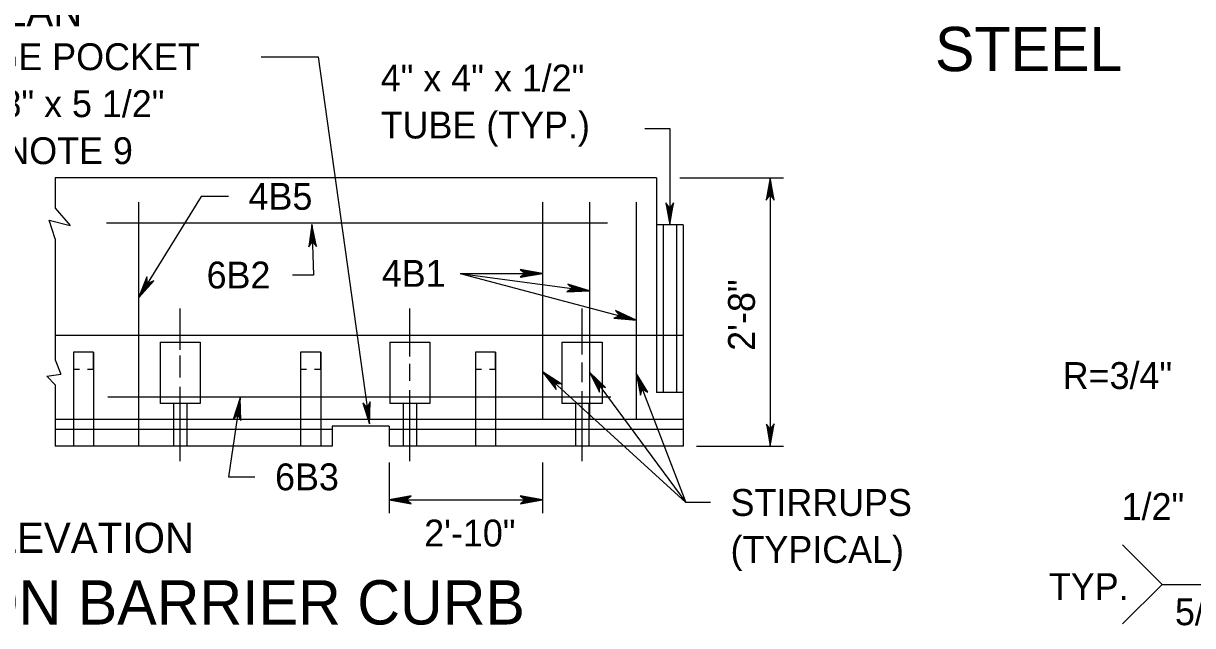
# Model space of a CAD drawing. Extents: x 499883 to 500983, y 499104 to 499764.
# Drawn here: x 500394.2 to 500568.6, y 499221.5 to 499311.2 of the extents above; entities that cross this region are included whole.
import ezdxf

# ---------------------------------------------------------------- set-up
doc = ezdxf.new("R2010")
doc.units = 0
for name, color, linetype in [('1', 7, 'Continuous'), ('24', 7, 'Continuous'), ('3', 7, 'Continuous'), ('5', 7, 'Continuous')]:
    doc.layers.add(name, color=color, linetype=linetype)

msp = doc.modelspace()

# ---------------------------------------------------------------- linework, layer by layer
at = {"layer": '1'}
for p, q in [((500417.6, 499262.54), (500417.6, 499268.7)), ((500451.89, 499261.59), (500451.89, 499268.7)), ((500477.56, 499261.86), (500477.56, 499268.7)), ((500417.6, 499258.44), (500417.6, 499261.72)), ((500451.89, 499257.94), (500451.89, 499260.49)), ((500477.56, 499257.75), (500477.56, 499260.67)), ((500417.6, 499245.98), (500417.6, 499257.07)), ((500451.89, 499245.98), (500451.89, 499256.57)), ((500477.56, 499245.98), (500477.56, 499256.39))]:
    msp.add_line(p, q, dxfattribs=at)
at = {"layer": '24'}
for points in [[(500490.64, 499281.18), (500491.22, 499284.46), (500490.64, 499283.67), (500490.07, 499284.44), (500490.64, 499281.18), (500490.64, 499281.4), (500491.18, 499284.36), (500490.64, 499283.61), (500490.12, 499284.31), (500490.63, 499281.52), (500490.64, 499281.63), (500491.09, 499284.17), (500490.64, 499283.6), (500490.19, 499284.18), (500490.64, 499281.68), (500490.63, 499281.79), (500491.03, 499284.01), (500490.64, 499283.57), (500490.24, 499284.01), (500490.63, 499282.1), (500490.63, 499282.29), (500490.94, 499283.84), (500490.65, 499283.54), (500490.33, 499283.86), (500490.64, 499282.32), (500490.65, 499282.49), (500490.85, 499283.66), (500490.63, 499283.44), (500490.4, 499283.68), (500490.64, 499282.65), (500490.66, 499282.82), (500490.79, 499283.52), (500490.64, 499283.41), (500490.46, 499283.6), (500490.64, 499282.91), (500490.75, 499283.36), (500490.63, 499283.3), (500490.5, 499283.5), (500490.63, 499283.02), (500490.7, 499283.32), (500490.6, 499283.19), (500490.54, 499283.34), (500490.64, 499283.2), (500490.65, 499283.27)], [(500437.28, 499281.23), (500437.49, 499273.71), (500434.37, 499273.71)], [(500437.28, 499281.23), (500436.79, 499277.89), (500437.35, 499278.7), (500437.95, 499277.94), (500437.28, 499281.23), (500437.29, 499281.01), (500436.83, 499277.98), (500437.36, 499278.76), (500437.9, 499278.07), (500437.3, 499280.89), (500437.29, 499280.78), (500436.91, 499278.19), (500437.36, 499278.78), (500437.82, 499278.2), (500437.29, 499280.73), (500437.31, 499280.62), (500436.97, 499278.35), (500437.35, 499278.8), (500437.77, 499278.37), (500437.32, 499280.3), (500437.33, 499280.11), (500437.05, 499278.52), (500437.34, 499278.84), (500437.68, 499278.52), (500437.31, 499280.07), (500437.31, 499279.9), (500437.14, 499278.7), (500437.36, 499278.94), (500437.6, 499278.7), (500437.32, 499279.73), (500437.31, 499279.57), (500437.19, 499278.85), (500437.35, 499278.97), (500437.53, 499278.78), (500437.33, 499279.48), (500437.23, 499279.01), (500437.36, 499279.08), (500437.49, 499278.88), (500437.35, 499279.36), (500437.28, 499279.06), (500437.38, 499279.19), (500437.44, 499279.04), (500437.34, 499279.19), (500437.33, 499279.11)], [(500411.42, 499270.29), (500413.68, 499272.83), (500412.76, 499272.46), (500412.67, 499273.43), (500411.42, 499270.29), (500411.53, 499270.48), (500413.6, 499272.78), (500412.72, 499272.41), (500412.64, 499273.29), (500411.59, 499270.59), (500411.66, 499270.68), (500413.42, 499272.65), (500412.71, 499272.4), (500412.64, 499273.14), (500411.69, 499270.72), (500411.73, 499270.82), (500413.27, 499272.54), (500412.7, 499272.37), (500412.59, 499272.97), (500411.9, 499271.1), (500412, 499271.26), (500413.11, 499272.44), (500412.69, 499272.34), (500412.58, 499272.8), (500412.03, 499271.28), (500412.14, 499271.43), (500412.94, 499272.34), (500412.62, 499272.26), (500412.55, 499272.6), (500412.21, 499271.57), (500412.31, 499271.71), (500412.81, 499272.25), (500412.61, 499272.23), (500412.56, 499272.49), (500412.35, 499271.79), (500412.69, 499272.13), (500412.54, 499272.14), (500412.54, 499272.38), (500412.39, 499271.9), (500412.62, 499272.12), (500412.47, 499272.06), (500412.49, 499272.22), (500412.5, 499272.05), (500412.55, 499272.1)], [(500471.66, 499273.95), (500468.31, 499274.54), (500469.11, 499273.95), (500468.33, 499273.37), (500471.66, 499273.95), (500471.44, 499273.95), (500468.41, 499274.5), (500469.18, 499273.94), (500468.47, 499273.41), (500471.32, 499273.94), (500471.21, 499273.95), (500468.61, 499274.41), (500469.19, 499273.94), (500468.59, 499273.49), (500471.16, 499273.95), (500471.05, 499273.94), (500468.78, 499274.35), (500469.22, 499273.95), (500468.77, 499273.54), (500470.72, 499273.93), (500470.53, 499273.94), (500468.94, 499274.26), (500469.25, 499273.96), (500468.92, 499273.63), (500470.5, 499273.95), (500470.32, 499273.96), (500469.13, 499274.17), (500469.36, 499273.93), (500469.11, 499273.71), (500470.16, 499273.95), (500469.99, 499273.97), (500469.27, 499274.11), (500469.39, 499273.94), (500469.19, 499273.77), (500469.9, 499273.95), (500469.43, 499274.06), (500469.5, 499273.94), (500469.29, 499273.81), (500469.78, 499273.93), (500469.48, 499274.01), (500469.6, 499273.91), (500469.46, 499273.85), (500469.6, 499273.94), (500469.53, 499273.96)], [(500478.66, 499271.34), (500475.42, 499272.37), (500476.13, 499271.68), (500475.28, 499271.21), (500478.66, 499271.34), (500478.44, 499271.36), (500475.51, 499272.32), (500476.19, 499271.66), (500475.42, 499271.23), (500478.32, 499271.37), (500478.21, 499271.4), (500475.7, 499272.21), (500476.21, 499271.66), (500475.55, 499271.29), (500478.16, 499271.41), (500478.04, 499271.4), (500475.85, 499272.12), (500476.23, 499271.67), (500475.73, 499271.32), (500477.72, 499271.45), (500477.54, 499271.47), (500476, 499272.01), (500476.27, 499271.67), (500475.9, 499271.39), (500477.51, 499271.49), (500477.33, 499271.53), (500476.17, 499271.89), (500476.37, 499271.63), (500476.09, 499271.44), (500477.17, 499271.54), (500477, 499271.58), (500476.31, 499271.81), (500476.4, 499271.64), (500476.19, 499271.48), (500476.91, 499271.57), (500476.46, 499271.75), (500476.51, 499271.61), (500476.29, 499271.51), (500476.79, 499271.57), (500476.5, 499271.69), (500476.61, 499271.57), (500476.46, 499271.53), (500476.62, 499271.61), (500476.54, 499271.63)], [(500485.65, 499266.99), (500482.57, 499268.42), (500483.19, 499267.64), (500482.28, 499267.28), (500485.65, 499266.99), (500485.44, 499267.04), (500482.65, 499268.36), (500483.25, 499267.62), (500482.42, 499267.29), (500485.32, 499267.06), (500485.21, 499267.11), (500482.82, 499268.22), (500483.26, 499267.62), (500482.57, 499267.33), (500485.16, 499267.12), (500485.05, 499267.13), (500482.96, 499268.11), (500483.29, 499267.62), (500482.75, 499267.34), (500484.74, 499267.22), (500484.56, 499267.26), (500483.1, 499267.99), (500483.33, 499267.62), (500482.92, 499267.38), (500484.53, 499267.29), (500484.36, 499267.35), (500483.25, 499267.85), (500483.42, 499267.57), (500483.12, 499267.41), (500484.2, 499267.38), (500484.04, 499267.44), (500483.38, 499267.75), (500483.45, 499267.57), (500483.22, 499267.44), (500483.95, 499267.44), (500483.52, 499267.67), (500483.56, 499267.53), (500483.33, 499267.46), (500483.83, 499267.46), (500483.55, 499267.61), (500483.65, 499267.48), (500483.49, 499267.46), (500483.66, 499267.51), (500483.59, 499267.55)], [(500471.66, 499259.27), (500473.69, 499256.64), (500473.51, 499257.59), (500474.46, 499257.5), (500471.66, 499259.27), (500471.83, 499259.13), (500473.66, 499256.73), (500473.47, 499257.64), (500474.33, 499257.55), (500471.92, 499259.06), (500471.99, 499258.97), (500473.57, 499256.93), (500473.45, 499257.65), (500474.18, 499257.58), (500472.03, 499258.94), (500472.12, 499258.88), (500473.49, 499257.09), (500473.43, 499257.66), (500474.03, 499257.66), (500472.35, 499258.66), (500472.49, 499258.54), (500473.43, 499257.26), (500473.4, 499257.68), (500473.86, 499257.7), (500472.5, 499258.5), (500472.63, 499258.38), (500473.36, 499257.45), (500473.34, 499257.76), (500473.67, 499257.77), (500472.75, 499258.28), (500472.86, 499258.16), (500473.29, 499257.58), (500473.31, 499257.78), (500473.57, 499257.78), (500472.94, 499258.11), (500473.2, 499257.72), (500473.24, 499257.86), (500473.47, 499257.82), (500473.03, 499258.05), (500473.2, 499257.79), (500473.18, 499257.95), (500473.32, 499257.89), (500473.16, 499257.92), (500473.2, 499257.86)], [(500478.66, 499259.23), (500480.14, 499256.25), (500480.14, 499257.23), (500481.05, 499256.95), (500478.66, 499259.23), (500478.79, 499259.06), (500480.12, 499256.35), (500480.11, 499257.28), (500480.94, 499257.03), (500478.87, 499258.97), (500478.92, 499258.87), (500480.07, 499256.56), (500480.1, 499257.29), (500480.81, 499257.09), (500478.95, 499258.83), (500479.03, 499258.76), (500480.03, 499256.73), (500480.08, 499257.31), (500480.66, 499257.19), (500479.22, 499258.5), (500479.33, 499258.35), (500480, 499256.92), (500480.05, 499257.33), (500480.51, 499257.26), (500479.33, 499258.32), (500479.43, 499258.17), (500479.96, 499257.11), (500480.01, 499257.43), (500480.34, 499257.37), (500479.53, 499258.05), (500479.62, 499257.91), (500479.93, 499257.26), (500479.99, 499257.45), (500480.24, 499257.4), (500479.68, 499257.85), (500479.87, 499257.41), (500479.93, 499257.54), (500480.15, 499257.45), (500479.76, 499257.76), (500479.88, 499257.48), (500479.89, 499257.64), (500480.02, 499257.56), (500479.86, 499257.62), (500479.89, 499257.55)], [(500485.65, 499259.08), (500486.28, 499255.82), (500486.54, 499256.75), (500487.35, 499256.24), (500485.65, 499259.08), (500485.74, 499258.88), (500486.29, 499255.92), (500486.53, 499256.81), (500487.26, 499256.35), (500485.79, 499258.77), (500485.81, 499258.67), (500486.3, 499256.13), (500486.52, 499256.83), (500487.15, 499256.44), (500485.83, 499258.62), (500485.88, 499258.52), (500486.3, 499256.31), (500486.51, 499256.85), (500487.04, 499256.58), (500486, 499258.23), (500486.06, 499258.06), (500486.32, 499256.49), (500486.49, 499256.88), (500486.91, 499256.69), (500486.06, 499258.02), (500486.11, 499257.85), (500486.34, 499256.69), (500486.47, 499256.98), (500486.77, 499256.83), (500486.18, 499257.71), (500486.22, 499257.55), (500486.35, 499256.84), (500486.45, 499257.01), (500486.69, 499256.89), (500486.27, 499257.47), (500486.33, 499257.01), (500486.42, 499257.11), (500486.61, 499256.97), (500486.32, 499257.37), (500486.36, 499257.06), (500486.41, 499257.22), (500486.52, 499257.1), (500486.38, 499257.2), (500486.39, 499257.13)], [(500426.57, 499255.39), (500424.82, 499243.64), (500428.77, 499243.64)], [(500426.57, 499255.39), (500425.5, 499252.19), (500426.2, 499252.89), (500426.66, 499252.04), (500426.57, 499255.39), (500426.55, 499255.17), (500425.56, 499252.28), (500426.22, 499252.95), (500426.63, 499252.18), (500426.54, 499255.05), (500426.51, 499254.95), (500425.67, 499252.46), (500426.22, 499252.97), (500426.58, 499252.31), (500426.5, 499254.9), (500426.5, 499254.79), (500425.77, 499252.62), (500426.22, 499252.99), (500426.55, 499252.49), (500426.45, 499254.47), (500426.43, 499254.28), (500425.87, 499252.77), (500426.21, 499253.03), (500426.49, 499252.65), (500426.4, 499254.25), (500426.37, 499254.08), (500425.99, 499252.93), (500426.25, 499253.13), (500426.44, 499252.85), (500426.35, 499253.91), (500426.31, 499253.75), (500426.07, 499253.07), (500426.25, 499253.16), (500426.4, 499252.94), (500426.32, 499253.66), (500426.14, 499253.22), (500426.27, 499253.27), (500426.37, 499253.05), (500426.32, 499253.55), (500426.19, 499253.25), (500426.31, 499253.37), (500426.35, 499253.21), (500426.28, 499253.37), (500426.25, 499253.3)], [(500445.86, 499251.52), (500445.98, 499254.84), (500445.51, 499253.98), (500444.84, 499254.66), (500445.86, 499251.52), (500445.82, 499251.73), (500445.95, 499254.74), (500445.52, 499253.92), (500444.91, 499254.54), (500445.8, 499251.84), (500445.8, 499251.96), (500445.89, 499254.53), (500445.52, 499253.91), (500445, 499254.42), (500445.79, 499252), (500445.76, 499252.11), (500445.85, 499254.36), (500445.53, 499253.88), (500445.07, 499254.26), (500445.72, 499252.42), (500445.69, 499252.61), (500445.79, 499254.19), (500445.54, 499253.85), (500445.18, 499254.13), (500445.7, 499252.64), (500445.69, 499252.82), (500445.72, 499254), (500445.53, 499253.75), (500445.28, 499253.96), (500445.66, 499252.97), (500445.65, 499253.14), (500445.68, 499253.85), (500445.54, 499253.72), (500445.35, 499253.88), (500445.62, 499253.22), (500445.67, 499253.69), (500445.55, 499253.61), (500445.4, 499253.79), (500445.59, 499253.33), (500445.62, 499253.64), (500445.54, 499253.5), (500445.46, 499253.64), (500445.57, 499253.51), (500445.58, 499253.58)], [(500448.77, 499240.21), (500452.09, 499239.63), (500451.3, 499240.21), (500452.07, 499240.79), (500448.77, 499240.21), (500448.99, 499240.22), (500452, 499239.67), (500451.24, 499240.22), (500451.94, 499240.75), (500449.11, 499240.23), (500449.22, 499240.21), (500451.8, 499239.76), (500451.22, 499240.22), (500451.81, 499240.67), (500449.27, 499240.21), (500449.38, 499240.23), (500451.63, 499239.82), (500451.19, 499240.21), (500451.64, 499240.62), (500449.7, 499240.23), (500449.89, 499240.23), (500451.47, 499239.91), (500451.16, 499240.2), (500451.49, 499240.53), (500449.92, 499240.21), (500450.1, 499240.2), (500451.29, 499240), (500451.06, 499240.23), (500451.3, 499240.46), (500450.26, 499240.21), (500450.43, 499240.2), (500451.14, 499240.06), (500451.02, 499240.22), (500451.22, 499240.4), (500450.52, 499240.21), (500450.98, 499240.1), (500450.91, 499240.23), (500451.12, 499240.36), (500450.63, 499240.23), (500450.94, 499240.15), (500450.81, 499240.25), (500450.96, 499240.31), (500450.81, 499240.22), (500450.89, 499240.2)], [(500471.66, 499240.21), (500468.34, 499240.8), (500469.13, 499240.21), (500468.36, 499239.64), (500471.66, 499240.21), (500471.44, 499240.21), (500468.43, 499240.76), (500469.2, 499240.21), (500468.49, 499239.68), (500471.32, 499240.2), (500471.21, 499240.21), (500468.63, 499240.67), (500469.21, 499240.21), (500468.62, 499239.76), (500471.16, 499240.21), (500471.05, 499240.2), (500468.8, 499240.6), (500469.24, 499240.21), (500468.79, 499239.81), (500470.73, 499240.2), (500470.54, 499240.2), (500468.97, 499240.52), (500469.27, 499240.22), (500468.94, 499239.89), (500470.51, 499240.21), (500470.33, 499240.22), (500469.15, 499240.43), (500469.37, 499240.2), (500469.13, 499239.97), (500470.17, 499240.21), (500470, 499240.23), (500469.29, 499240.37), (500469.41, 499240.21), (500469.21, 499240.03), (500469.91, 499240.21), (500469.45, 499240.32), (500469.52, 499240.2), (500469.31, 499240.07), (500469.8, 499240.2), (500469.49, 499240.27), (500469.62, 499240.17), (500469.47, 499240.11), (500469.62, 499240.21), (500469.54, 499240.22)]]:
    msp.add_lwpolyline(points, dxfattribs=at)
at = {"layer": '3'}
for points in [[(500401.71, 499262.2), (500401.71, 499259.68), (500402.59, 499259.69)], [(500403.79, 499259.69), (500404.71, 499259.69), (500404.71, 499262.2), (500401.71, 499262.2)], [(500435.58, 499262.2), (500435.58, 499259.68), (500436.46, 499259.69)], [(500437.66, 499259.69), (500438.58, 499259.69), (500438.58, 499262.2), (500435.58, 499262.2)], [(500461.66, 499262.2), (500461.66, 499259.68), (500462.54, 499259.69)], [(500463.74, 499259.69), (500464.66, 499259.69), (500464.66, 499262.2), (500461.66, 499262.2)]]:
    msp.add_lwpolyline(points, dxfattribs=at)
at = {"layer": '5'}
for p, q in [((500486.91, 499295.55), (500490.64, 499295.55)), ((500488.64, 499288.18), (500398.99, 499288.18)), ((500398.99, 499288.18), (500398.99, 499283.65)), ((500488.64, 499288.18), (500488.64, 499281.18)), ((500492.12, 499288.18), (500507.63, 499288.18)), ((500505.63, 499288.18), (500505.63, 499248.21)), ((500398.99, 499283.65), (500401.23, 499281.07)), ((500411.42, 499284.56), (500411.42, 499248.21)), ((500471.66, 499284.56), (500471.66, 499252.2)), ((500478.66, 499284.56), (500478.66, 499252.2)), ((500485.65, 499284.56), (500485.65, 499252.2)), ((500398.99, 499279.1), (500398.06, 499281.87)), ((500398.06, 499281.87), (500401.23, 499281.07)), ((500406.62, 499281.5), (500481.36, 499281.5)), ((500488.64, 499281.18), (500488.64, 499256.2)), ((500492.64, 499281.18), (500488.64, 499281.18)), ((500489.64, 499281.18), (500489.64, 499256.2)), ((500491.64, 499281.18), (500491.64, 499256.2)), ((500492.64, 499281.18), (500492.64, 499248.21)), ((500398.99, 499279.1), (500398.99, 499261.09)), ((500459.39, 499273.95), (500478.66, 499271.34)), ((500459.39, 499273.95), (500485.65, 499266.99)), ((500459.39, 499273.95), (500471.66, 499273.95)), ((500492.64, 499264.7), (500398.99, 499264.7)), ((500414.61, 499263.7), (500414.61, 499254.56)), ((500414.61, 499263.7), (500420.6, 499263.7)), ((500420.6, 499263.7), (500420.6, 499254.56)), ((500448.89, 499263.7), (500448.89, 499254.56)), ((500448.89, 499263.7), (500454.88, 499263.7)), ((500454.88, 499263.7), (500454.88, 499254.56)), ((500474.56, 499263.7), (500474.56, 499254.56)), ((500474.56, 499263.7), (500480.56, 499263.7)), ((500480.56, 499263.7), (500480.56, 499254.56)), ((500398.99, 499261.09), (500399.84, 499258.92)), ((500401.71, 499262.2), (500401.71, 499248.21)), ((500404.71, 499262.2), (500404.71, 499248.21)), ((500435.58, 499262.2), (500435.58, 499248.21)), ((500438.58, 499262.2), (500438.58, 499248.21)), ((500461.66, 499262.2), (500461.66, 499248.21)), ((500464.66, 499262.2), (500464.66, 499248.21)), ((500478.66, 499259.23), (500493.03, 499239.82)), ((500485.65, 499259.08), (500493.03, 499239.82)), ((500397.72, 499258.65), (500399.84, 499258.92)), ((500398.99, 499257.33), (500397.72, 499258.65)), ((500398.99, 499257.33), (500398.99, 499248.21)), ((500406.83, 499255.56), (500481.85, 499255.56)), ((500492.64, 499256.2), (500488.64, 499256.2)), ((500420.6, 499254.56), (500414.61, 499254.56)), ((500416.6, 499254.56), (500416.6, 499248.21)), ((500418.6, 499254.56), (500418.6, 499248.21)), ((500454.88, 499254.56), (500448.89, 499254.56)), ((500450.89, 499254.56), (500450.89, 499248.21)), ((500452.89, 499254.56), (500452.89, 499248.21)), ((500480.56, 499254.56), (500474.56, 499254.56)), ((500476.56, 499254.56), (500476.56, 499248.21)), ((500478.56, 499254.56), (500478.56, 499248.21)), ((500429.82, 499252.2), (500398.99, 499252.2)), ((500405.75, 499252.2), (500400.51, 499252.2)), ((500492.64, 499252.2), (500429.82, 499252.2)), ((500440.27, 499250.71), (500398.99, 499250.71)), ((500448.77, 499251.21), (500440.27, 499251.21)), ((500440.27, 499251.21), (500440.27, 499248.21)), ((500448.77, 499251.21), (500448.77, 499248.21)), ((500492.64, 499250.71), (500448.77, 499250.71)), ((500440.27, 499248.21), (500398.99, 499248.21)), ((500405.75, 499248.21), (500400.51, 499248.21)), ((500492.64, 499248.21), (500448.77, 499248.21)), ((500494.62, 499248.21), (500507.63, 499248.21)), ((500448.77, 499245.79), (500448.77, 499238.22)), ((500471.66, 499245.79), (500471.66, 499238.22)), ((500448.77, 499240.21), (500471.66, 499240.21)), ((500558.17, 499233.5), (500564.06, 499227.61)), ((500564.06, 499227.61), (500558.17, 499221.72)), ((500564.06, 499227.61), (500580.51, 499227.61))]:
    msp.add_line(p, q, dxfattribs=at)
for points in [[(500429.71, 499306.22), (500438.21, 499306.22), (500445.86, 499251.52)], [(500490.64, 499295.55), (500490.64, 499281.18)], [(500505.63, 499288.18), (500505.04, 499284.85), (500505.63, 499285.65), (500506.21, 499284.87), (500505.63, 499288.18), (500505.64, 499287.96), (500505.09, 499284.95), (500505.64, 499285.71), (500506.16, 499285), (500505.65, 499287.84), (500505.63, 499287.73), (500505.17, 499285.15), (500505.64, 499285.73), (500506.09, 499285.13), (500505.63, 499287.68), (500505.65, 499287.57), (500505.24, 499285.31), (500505.63, 499285.75), (500506.04, 499285.3), (500505.65, 499287.24), (500505.65, 499287.06), (500505.32, 499285.48), (500505.62, 499285.79), (500505.95, 499285.46), (500505.63, 499287.02), (500505.62, 499286.85), (500505.42, 499285.66), (500505.65, 499285.89), (500505.88, 499285.64), (500505.63, 499286.68), (500505.61, 499286.52), (500505.48, 499285.8), (500505.64, 499285.92), (500505.82, 499285.73), (500505.63, 499286.43), (500505.52, 499285.96), (500505.65, 499286.03), (500505.77, 499285.83), (500505.65, 499286.31), (500505.57, 499286.01), (500505.67, 499286.13), (500505.73, 499285.99), (500505.64, 499286.13), (500505.62, 499286.06)], [(500424.82, 499285.43), (500420.73, 499285.43), (500411.42, 499270.29)], [(500496.71, 499239.82), (500493.03, 499239.82), (500471.66, 499259.27)], [(500505.63, 499248.21), (500506.22, 499251.53), (500505.63, 499250.74), (500505.05, 499251.51), (500505.63, 499248.21), (500505.62, 499248.43), (500506.17, 499251.44), (500505.62, 499250.68), (500505.1, 499251.38), (500505.61, 499248.55), (500505.63, 499248.66), (500506.09, 499251.24), (500505.62, 499250.66), (500505.17, 499251.25), (500505.63, 499248.71), (500505.61, 499248.82), (500506.02, 499251.07), (500505.63, 499250.63), (500505.23, 499251.08), (500505.61, 499249.14), (500505.61, 499249.33), (500505.94, 499250.91), (500505.64, 499250.6), (500505.31, 499250.93), (500505.63, 499249.36), (500505.64, 499249.54), (500505.84, 499250.73), (500505.61, 499250.5), (500505.39, 499250.74), (500505.63, 499249.7), (500505.65, 499249.87), (500505.78, 499250.58), (500505.62, 499250.46), (500505.45, 499250.66), (500505.63, 499249.96), (500505.74, 499250.42), (500505.61, 499250.35), (500505.49, 499250.56), (500505.61, 499250.07), (500505.69, 499250.38), (500505.59, 499250.25), (500505.53, 499250.4), (500505.62, 499250.25), (500505.64, 499250.33)]]:
    msp.add_lwpolyline(points, dxfattribs=at)

# ---------------------------------------------------------------- texts
for s, height, p in [('PLAN', 4.5, (500387.31, 499310.74)), ('STEEL', 6.6, (500530.2, 499304.08)), ('DRAINAGE POCKET', 4, (500369.11, 499304.23)), ('4" x 4" x 1/2"', 4, (500447.53, 499301.05)), ('2 5/8" x 5 1/2"', 4, (500382.04, 499297.23)), ('TUBE (TYP.)', 4, (500447.53, 499294.05)), ('SEE NOTE 9', 4, (500379.06, 499290.23)), ('4B5', 4, (500427.82, 499283.43)), ('6B2', 4, (500421.56, 499271.71)), ('4B1', 4, (500447.69, 499271.95)), ('R=3/4"', 4, (500549.25, 499256.73)), ('6B3', 4, (500431.77, 499241.64)), ('STIRRUPS', 4, (500499.71, 499237.82)), ('1/2"', 4, (500558.04, 499237.21)), ('ELEVATION', 4.5, (500385.92, 499232.32)), ('2\'-10"', 4, (500454.01, 499233.27)), ('(TYPICAL)', 4, (500499.71, 499230.82)), ('CONSTRUCTION BARRIER CURB', 6.6001, (500328.8, 499221.64)), ('TYP.', 4, (500547.19, 499225.29)), ('5/16', 4, (500565.99, 499221.54))]:
    msp.add_text(s, height=height, dxfattribs=at).set_placement(p)
msp.add_text('2\'-8"', height=4, rotation=90, dxfattribs=at).set_placement((500503.34, 499262.41))

doc.saveas('drawing.dxf')
